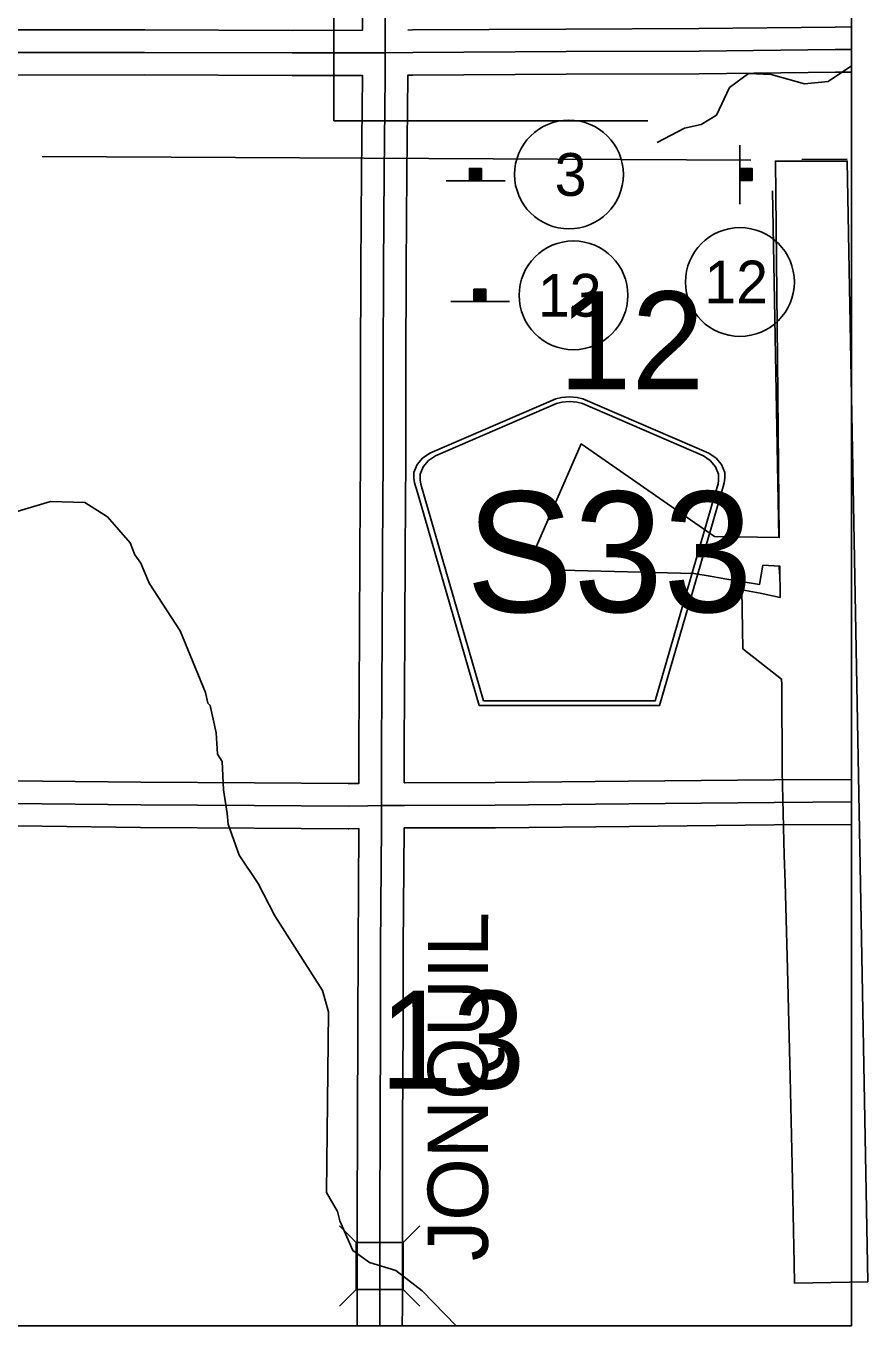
# Model space of a CAD drawing. Extents: x -2251611 to -2054719, y -2227156 to -2099355.
# Drawn here: x -2129880 to -2123980, y -2144316 to -2135199 of the extents above; entities that cross this region are included whole.
import ezdxf

# ---------------------------------------------------------------- set-up
doc = ezdxf.new("R2010")
doc.units = 0
for name, color, linetype in [('Default', 7, 'Continuous'), ('dsnTextFinalPlan', 7, 'Continuous'), ('dsnTextNote', 7, 'Continuous'), ('tdCoCorpBndry', 7, 'Continuous'), ('tdCoHydroRiver', 7, 'Continuous'), ('tdCoSecRdTxt', 7, 'Continuous'), ('tdCoSecRteBand', 7, 'Continuous'), ('tdCoSectLinePart', 7, 'Continuous'), ('tdCoSectNmbr', 7, 'Continuous'), ('tdCoShieldCoRteHrd', 7, 'Continuous'), ('tdCoStrucSec', 7, 'Continuous'), ('tdCoSurfAsphalt', 7, 'Continuous'), ('tdCoSurfConc', 7, 'Continuous'), ('tdCoSurfGravel', 7, 'Continuous')]:
    doc.layers.add(name, color=color, linetype=linetype)

msp = doc.modelspace()

# ---------------------------------------------------------------- linework, layer by layer
at = {"layer": 'Default'}
for p, q in [((-2127721.9, -2125120.3), (-2127721.9, -2135863.1)), ((-2127721.9, -2135863.1), (-2125522.8, -2135863.1))]:
    msp.add_line(p, q, dxfattribs=at)
at = {"layer": 'dsnTextFinalPlan'}
for p, q in [((-2124877.4, -2136035.2), (-2124877.4, -2136447.7)), ((-2126772.3, -2136204), (-2126688.5, -2136204)), ((-2126688.5, -2136208.8), (-2126772.3, -2136208.8)), ((-2126772.3, -2136212.2), (-2126688.5, -2136212.2)), ((-2126688.5, -2136216.9), (-2126772.3, -2136216.9)), ((-2126772.3, -2136220.3), (-2126688.5, -2136220)), ((-2126688.5, -2136226.5), (-2126772.3, -2136226.8)), ((-2126772.3, -2136229.9), (-2126688.5, -2136229.9)), ((-2126688.5, -2136236.3), (-2126772.3, -2136236.3)), ((-2124871.2, -2136281.9), (-2124871.2, -2136198.1)), ((-2124867, -2136198.1), (-2124867, -2136281.9)), ((-2124863, -2136281.9), (-2124863, -2136198.1)), ((-2124859.1, -2136198.1), (-2124859.1, -2136281.9)), ((-2124855.7, -2136281.9), (-2124855.7, -2136198.1)), ((-2124852.6, -2136198.1), (-2124852.6, -2136281.9)), ((-2124847.6, -2136281.9), (-2124847.6, -2136198.1)), ((-2124843.6, -2136198.1), (-2124843.6, -2136281.9)), ((-2124840.2, -2136281.9), (-2124840.5, -2136198.1)), ((-2124835.5, -2136198.1), (-2124835.5, -2136281.9)), ((-2124829.8, -2136281.9), (-2124829.8, -2136198.1)), ((-2124823.4, -2136198.1), (-2124823.4, -2136281.9)), ((-2124820, -2136281.9), (-2124820.3, -2136198.1)), ((-2124813.8, -2136198.1), (-2124813.5, -2136281.9)), ((-2124810.4, -2136281.9), (-2124810.4, -2136198.1)), ((-2124805.6, -2136198.1), (-2124805.6, -2136281.9)), ((-2124802.3, -2136281.9), (-2124802.3, -2136198.1)), ((-2124797.5, -2136198.1), (-2124797.5, -2136281.9)), ((-2126935.2, -2136283.9), (-2126522.7, -2136283.9)), ((-2126772.3, -2136242), (-2126688.5, -2136242)), ((-2126688.5, -2136246.8), (-2126772.3, -2136247)), ((-2126772.3, -2136250.1), (-2126688.5, -2136250.1)), ((-2126688.5, -2136254.1), (-2126772.3, -2136254.1)), ((-2126772.3, -2136259.1), (-2126688.5, -2136259.1)), ((-2126688.5, -2136262.2), (-2126772.3, -2136262.2)), ((-2126772.3, -2136265.6), (-2126688.5, -2136265.6)), ((-2126688.5, -2136269.5), (-2126772.3, -2136269.5)), ((-2126772.3, -2136273.5), (-2126688.5, -2136273.5)), ((-2126688.5, -2136277.7), (-2126772.3, -2136277.7)), ((-2126740.6, -2137051.4), (-2126656.8, -2137051.4)), ((-2126656.8, -2137056.2), (-2126740.6, -2137056.2)), ((-2126903.5, -2137131.3), (-2126491, -2137131.3)), ((-2126740.6, -2137059.6), (-2126656.8, -2137059.6)), ((-2126656.8, -2137064.3), (-2126740.6, -2137064.3)), ((-2126740.6, -2137067.7), (-2126656.8, -2137067.4)), ((-2126656.8, -2137073.9), (-2126740.6, -2137074.2)), ((-2126740.6, -2137077.3), (-2126656.8, -2137077.3)), ((-2126656.8, -2137083.7), (-2126740.6, -2137083.7)), ((-2126740.6, -2137089.4), (-2126656.8, -2137089.4)), ((-2126656.8, -2137094.1), (-2126740.6, -2137094.4)), ((-2126740.6, -2137097.5), (-2126656.8, -2137097.5)), ((-2126656.8, -2137101.5), (-2126740.6, -2137101.5)), ((-2126740.6, -2137106.5), (-2126656.8, -2137106.5)), ((-2126656.8, -2137109.6), (-2126740.6, -2137109.6)), ((-2126740.6, -2137113), (-2126656.8, -2137113)), ((-2126656.8, -2137116.9), (-2126740.6, -2137116.9)), ((-2126740.6, -2137120.9), (-2126656.8, -2137120.9)), ((-2126656.8, -2137125.1), (-2126740.6, -2137125.1))]:
    msp.add_line(p, q, dxfattribs=at)
for points in [[(-2126688.5, -2136282.5), (-2126772.9, -2136282.5), (-2126772.9, -2136198.1), (-2126688.5, -2136198.1)], [(-2124876, -2136281.9), (-2124876, -2136197.5), (-2124791.6, -2136197.5), (-2124791.6, -2136281.9)], [(-2126656.8, -2137129.9), (-2126741.2, -2137129.9), (-2126741.2, -2137045.5), (-2126656.8, -2137045.5)]]:
    msp.add_lwpolyline(points, close=True, dxfattribs=at)
at = {"layer": 'dsnTextNote'}
msp.add_lwpolyline([(-2138305.1, -2118109.7), (-2124095.9, -2118109.7), (-2124095.9, -2144315.9), (-2146959.9, -2144315.9), (-2146959.9, -2118109.7), (-2138305.1, -2118109.7)], dxfattribs=at)
for centre in [(-2126075.2, -2136240.4), (-2124877.4, -2136994.8), (-2126043.5, -2137087.8)]:
    msp.add_circle(centre, 381.4, dxfattribs=at)
at = {"layer": 'tdCoCorpBndry'}
msp.add_lwpolyline([(-2123980, -2144006), (-2124125.3, -2136146.6), (-2124628.5, -2136146.8), (-2124614.5, -2137535.3), (-2124601.9, -2138787.1), (-2125055.4, -2138778.7), (-2125990.9, -2138130.3), (-2126318.2, -2138884.6), (-2126176.8, -2139009), (-2126127.4, -2139014.3), (-2125201, -2139038.6), (-2125087, -2139058), (-2124982.7, -2139075), (-2124740, -2139115), (-2124716.3, -2138981.1), (-2124598.8, -2138987.2), (-2124596.1, -2139206.8), (-2124735.6, -2139175.8), (-2124864.7, -2139153.5), (-2124857.9, -2139566.9), (-2124585.9, -2139779.3), (-2124584.8, -2139818.5), (-2124580.9, -2140424), (-2124566.2, -2141014), (-2124561.4, -2141205.2), (-2124556.6, -2141375.3), (-2124544.4, -2141810.7), (-2124524.9, -2142568.5), (-2124511.9, -2143185.7), (-2124498.2, -2143878.3), (-2124495, -2144014.4)], close=True, dxfattribs=at)
at = {"layer": 'tdCoHydroRiver'}
for points in [[(-2125457.6, -2136016.1), (-2125266.2, -2135915.7), (-2125149.6, -2135890.4), (-2125041.5, -2135823.5), (-2124950.2, -2135631.6), (-2124817.2, -2135531.3), (-2124658.8, -2135539.3), (-2124425.3, -2135605.4), (-2124258.8, -2135588.3), (-2124095.9, -2135479.2)], [(-2129959.4, -2138609.7), (-2129709.6, -2138534.1), (-2129467.9, -2138541.8), (-2129309.4, -2138641.5), (-2129150.7, -2138824.4), (-2129117.1, -2138907.7), (-2129075.3, -2138965.9), (-2129016.7, -2139107.4), (-2128799.2, -2139440.2), (-2128623.2, -2139873.1), (-2128606.4, -2139948), (-2128589.7, -2139964.6), (-2128547.6, -2140156.2), (-2128538.9, -2140306.2), (-2128505.4, -2140356.1), (-2128496.6, -2140556), (-2128471.3, -2140722.6), (-2128462.7, -2140797.6), (-2128387.2, -2141014.1), (-2128253.4, -2141213.7), (-2128136.3, -2141438.4), (-2127801.7, -2141962.6), (-2127759.7, -2142112.5), (-2127773.4, -2143379.1), (-2127698.1, -2143512.2), (-2127681.2, -2143578.8), (-2127589.1, -2143786.9), (-2127472.2, -2143870), (-2127288.8, -2143927.9), (-2127105.1, -2144069.1), (-2126865.4, -2144315.9)]]:
    msp.add_lwpolyline(points, dxfattribs=at)
at = {"layer": 'tdCoSecRteBand'}
for points in [[(-2130187.6, -2135227.2), (-2129049.3, -2135225.9), (-2129048.9, -2135225.9), (-2129048.5, -2135225.9), (-2128013.8, -2135229.8), (-2127522.4, -2135228.7), (-2127522.4, -2135228.1), (-2127522.4, -2135130.1)], [(-2127205.6, -2135227.4), (-2127171, -2135227.2), (-2126096.9, -2135220.7), (-2126096.8, -2135220.7), (-2126096.6, -2135220.7), (-2125164.9, -2135216.8), (-2124211, -2135206.4), (-2124210.5, -2135206.4), (-2124210.1, -2135206.4), (-2124095.9, -2135205.8)], [(-2127622.9, -2140511.7), (-2127548.7, -2140510.3), (-2127548.7, -2140509.7), (-2127547.1, -2140509.7), (-2127547.1, -2140508.1), (-2127547.1, -2140266.2), (-2127547.1, -2140265.8), (-2127547.1, -2140265.5), (-2127543.2, -2139451.7), (-2127540.6, -2138882.7), (-2127540.6, -2138882.4), (-2127540.6, -2138882.2), (-2127535.4, -2138227.8), (-2127535.4, -2137595.7), (-2127535.4, -2137595.4), (-2127535.4, -2137595.1), (-2127532.8, -2136890.7), (-2127532.8, -2136890.5), (-2127532.8, -2136890.3), (-2127528.9, -2136227.5), (-2127528.9, -2136227.2), (-2127528.9, -2136226.9), (-2127522.4, -2135553.2), (-2127522.4, -2135545.5), (-2128013.6, -2135546.6), (-2128014.1, -2135546.6), (-2128014.5, -2135546.6), (-2129049.3, -2135542.7), (-2130188.2, -2135544)], [(-2124095.9, -2135522.6), (-2124208, -2135523.2), (-2125162, -2135533.6), (-2125162.5, -2135533.6), (-2125163, -2135533.6), (-2126095.2, -2135537.5), (-2127169.2, -2135544), (-2127169.4, -2135544), (-2127169.5, -2135544), (-2127205.6, -2135544.2), (-2127205.6, -2135544.9), (-2127205.6, -2135554), (-2127205.6, -2135554.8), (-2127205.6, -2135555.5), (-2127212.1, -2136229.7), (-2127216, -2136892), (-2127218.6, -2137596), (-2127218.6, -2138228.5), (-2127218.6, -2138229.1), (-2127218.6, -2138229.7), (-2127223.8, -2138884.4), (-2127226.4, -2139453.2), (-2127226.4, -2139453.2), (-2127226.4, -2139453.2), (-2127230.3, -2140266.6), (-2127230.3, -2140506.5)], [(-2130817.6, -2140489.6), (-2129765.6, -2140494.8), (-2129765.1, -2140494.8), (-2129764.6, -2140494.8), (-2129074.9, -2140502.6), (-2128279.8, -2140507.8), (-2127622.9, -2140511.7)], [(-2127230.3, -2140506.5), (-2127230.3, -2140506.5), (-2127229.6, -2140506.5), (-2127229, -2140506.5), (-2126592.9, -2140505.2), (-2125657.3, -2140496.1), (-2124639.2, -2140485.7), (-2124638.8, -2140485.7), (-2124638.5, -2140485.6), (-2124095.9, -2140482.4)], [(-2127560.2, -2144315.9), (-2127558.9, -2144176.9), (-2127558.9, -2143548.8), (-2127558.9, -2143548.6), (-2127558.9, -2143548.5), (-2127557.6, -2142900), (-2127557.6, -2142899.9), (-2127557.6, -2142899.7), (-2127554.9, -2142211.1), (-2127553.6, -2141659.1), (-2127553.6, -2141658.7), (-2127553.6, -2141658.2), (-2127547.3, -2140827.1), (-2127618.9, -2140828.5), (-2127620.9, -2140828.5), (-2127622.8, -2140828.5), (-2128281.7, -2140824.6), (-2128281.7, -2140824.6), (-2128281.8, -2140824.6), (-2129077.4, -2140819.4), (-2129077.7, -2140819.4), (-2129078.1, -2140819.4), (-2129767.7, -2140811.6), (-2130819.3, -2140806.3)], [(-2124095.9, -2140799.2), (-2124636.3, -2140802.4), (-2125654.1, -2140812.9), (-2125654.2, -2140812.9), (-2125654.2, -2140812.9), (-2126590.4, -2140822), (-2126591, -2140822), (-2126591.6, -2140822), (-2127227.7, -2140823.3), (-2127230.3, -2140823.3), (-2127230.3, -2140824.9), (-2127230.4, -2140824.9), (-2127236.8, -2141660.3), (-2127238.1, -2142211.9), (-2127238.1, -2142212), (-2127238.1, -2142212.1), (-2127240.8, -2142900.8), (-2127242.1, -2143548.9), (-2127242.1, -2144177.7), (-2127242.1, -2144178.4), (-2127242.1, -2144179.2), (-2127243.3, -2144315.9)]]:
    msp.add_lwpolyline(points, dxfattribs=at)
at = {"layer": 'tdCoSectLinePart'}
for points in [[(-2129766.5, -2136115.2), (-2124800.9, -2136139.6)], [(-2124443.1, -2136135.8), (-2124125.6, -2136132.4)], [(-2124649.5, -2136354.7), (-2124605.4, -2138787.1)], [(-2124601.7, -2138987.1), (-2124600.7, -2139044.3)]]:
    msp.add_lwpolyline(points, dxfattribs=at)
at = {"layer": 'tdCoShieldCoRteHrd'}
for points in [[(-2126704.6, -2139965.1), (-2127137.3, -2138471.4), (-2127157.7, -2138401.9), (-2127161.6, -2138370.9), (-2127161.6, -2138329.6), (-2127139.2, -2138275.1), (-2127100.8, -2138230.3), (-2127050.2, -2138195.1), (-2126167, -2137813.1), (-2126127.3, -2137804.4), (-2126072.3, -2137799.6), (-2126017.2, -2137804.4), (-2125977.6, -2137813.1), (-2125094.3, -2138195.1), (-2125043.8, -2138230.3), (-2125005.4, -2138275.1), (-2124983, -2138329.6), (-2124983, -2138370.9), (-2124986.8, -2138401.9), (-2125007.3, -2138471.4), (-2125439.9, -2139965.1)], [(-2126673.7, -2139931.6), (-2127094.7, -2138478.2), (-2127114.3, -2138411.5), (-2127118, -2138381.7), (-2127118, -2138342), (-2127096.5, -2138289.8), (-2127059.6, -2138246.8), (-2127011.1, -2138212.9), (-2126163.2, -2137846.2), (-2126125.1, -2137837.9), (-2126072.3, -2137833.3), (-2126019.4, -2137837.9), (-2125981.3, -2137846.2), (-2125133.5, -2138212.9), (-2125084.9, -2138246.8), (-2125048.1, -2138289.8), (-2125026.5, -2138342), (-2125026.5, -2138381.7), (-2125030.2, -2138411.5), (-2125049.9, -2138478.2), (-2125470.9, -2139931.6)]]:
    msp.add_lwpolyline(points, close=True, dxfattribs=at)
at = {"layer": 'tdCoStrucSec'}
for p, q in [((-2127567.5, -2143730.2), (-2127684.4, -2143613.3)), ((-2127237, -2143730.2), (-2127120.1, -2143613.3)), ((-2127567.5, -2144060.7), (-2127684.4, -2144177.6)), ((-2127237, -2144060.7), (-2127120.1, -2144177.6))]:
    msp.add_line(p, q, dxfattribs=at)
msp.add_lwpolyline([(-2127567.5, -2144060.7), (-2127567.5, -2143730.2), (-2127237, -2143730.2), (-2127237, -2144060.7)], close=True, dxfattribs=at)
at = {"layer": 'tdCoSurfAsphalt'}
msp.add_lwpolyline([(-2132351.6, -2135653.7), (-2132271.7, -2135577), (-2132232.6, -2135548.6), (-2132192.2, -2135522.2), (-2132150.5, -2135497.7), (-2132107.7, -2135475.3), (-2132063.8, -2135455), (-2132019, -2135436.8), (-2131973.4, -2135420.8), (-2131927.1, -2135407.1), (-2131880.1, -2135395.6), (-2131832.7, -2135386.3), (-2131784.8, -2135379.4), (-2131736.7, -2135374.9), (-2131688.4, -2135372.6), (-2131451.4, -2135372.6), (-2130878.5, -2135377.8), (-2130188.4, -2135385.6), (-2129049.1, -2135384.3), (-2128013.9, -2135388.2), (-2127452.7, -2135386.9), (-2127364, -2135386.5)], dxfattribs=at)
at = {"layer": 'tdCoSurfConc'}
msp.add_lwpolyline([(-2127401.8, -2144315.9), (-2127400.5, -2144177.7), (-2127400.5, -2143548.8), (-2127399.2, -2142900.3), (-2127396.5, -2142211.5), (-2127395.2, -2141659.5), (-2127388.7, -2140810.5), (-2127388.7, -2140666.5), (-2127388.7, -2140266.2), (-2127384.8, -2139452.4), (-2127382.2, -2138883.4), (-2127377, -2138228.5), (-2127377, -2137595.7), (-2127374.4, -2136891.2), (-2127370.5, -2136228.5), (-2127364, -2135554), (-2127364, -2135386.5), (-2127364, -2135129.5)], dxfattribs=at)
at = {"layer": 'tdCoSurfGravel'}
for points in [[(-2127364, -2135386.5), (-2127170.2, -2135385.6), (-2126096, -2135379.1), (-2125163.7, -2135375.2), (-2124209.3, -2135364.8), (-2124095.9, -2135364.2)], [(-2132650.1, -2140639.1), (-2132468.2, -2140634.9), (-2131420.1, -2140644), (-2130818.5, -2140648), (-2129766.4, -2140653.2), (-2129076.3, -2140661), (-2128280.8, -2140666.2), (-2127621.9, -2140670.1), (-2127483.9, -2140667.5), (-2127388.7, -2140666.5), (-2127228.7, -2140664.9), (-2126592, -2140663.6), (-2125655.8, -2140654.5), (-2124637.5, -2140644), (-2124095.9, -2140640.8)]]:
    msp.add_lwpolyline(points, dxfattribs=at)

# ---------------------------------------------------------------- texts
at = {"layer": 'dsnTextNote'}
for s, p in [('3', (-2126175.5, -2136390.4)), ('12', (-2125126.5, -2137144.8)), ('13', (-2126292.6, -2137237.8))]:
    msp.add_text(s, height=300, dxfattribs=at).set_placement(p)
at = {"layer": 'tdCoSecRdTxt'}
msp.add_text('JONQUIL', height=422.4, rotation=89.95818, dxfattribs=at).set_placement((-2126643.3, -2143860.6))
at = {"layer": 'tdCoSectNmbr'}
for s, rotation, p in [('12', 0.02074, (-2126147.9, -2137747.1)), ('13', 0.02063, (-2127402.4, -2142651.5))]:
    msp.add_text(s, height=686.4, rotation=rotation, dxfattribs=at).set_placement(p)
at = {"layer": 'tdCoShieldCoRteHrd'}
msp.add_text('S33', height=844.8, dxfattribs=at).set_placement((-2126797.3, -2139309))

doc.saveas('drawing.dxf')
